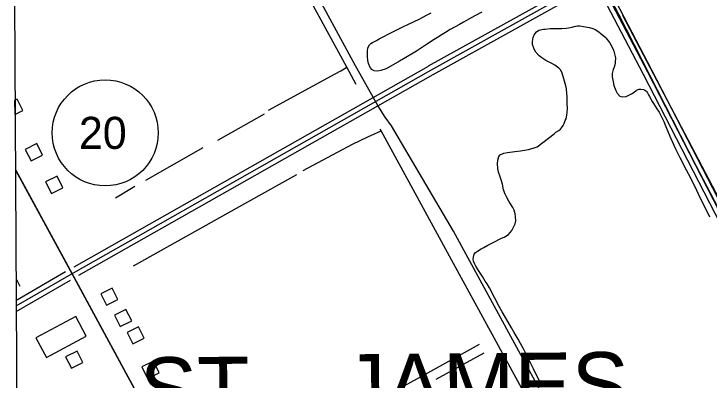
# Model space of a CAD drawing. Extents: x 3477039 to 3515015, y 546746 to 572297.
# Drawn here: x 3481169 to 3483333, y 568545 to 569685 of the extents above; entities that cross this region are included whole.
import ezdxf

# ---------------------------------------------------------------- set-up
doc = ezdxf.new("R2010")
doc.units = 0
for name, color, linetype in [('V-BLDG-OTLN', 7, 'Continuous'), ('V-DTCH-CNTR', 7, 'Continuous'), ('V-GRID-FRAM', 7, 'Continuous'), ('V-ROAD-CNTR', 7, 'Continuous'), ('V-ROAD-IDEN', 7, 'Continuous'), ('V-SITE-VEGE', 7, 'Continuous'), ('V-TOPO-GNAM-IDEN', 7, 'Continuous'), ('V-TOPO-SHOR', 7, 'Continuous')]:
    doc.layers.add(name, color=color, linetype=linetype)

msp = doc.modelspace()

# ---------------------------------------------------------------- linework, layer by layer
at = {"layer": 'V-BLDG-OTLN'}
msp.add_line((3481170.7, 569415.7), (3481170.9, 569371.1), dxfattribs=at)
msp.add_lwpolyline([(3481170.9, 569371.1), (3481196.2, 569383.7), (3481178.3, 569419.5), (3481170.7, 569415.7)], dxfattribs=at)
for points in [[(3481204, 569263), (3481221.8, 569227.2), (3481257.6, 569245.1), (3481239.7, 569280.9)], [(3481267.3, 569161.6), (3481285.1, 569125.8), (3481320.9, 569143.7), (3481303, 569179.4)], [(3481438.8, 568813.3), (3481456.6, 568777.5), (3481492.4, 568795.4), (3481474.5, 568831.2)], [(3481481.6, 568746.8), (3481499.4, 568711.1), (3481535.2, 568728.9), (3481517.3, 568764.7)], [(3481361.2, 568742.7), (3481237, 568676), (3481269.7, 568615), (3481394, 568681.7)], [(3481520.7, 568692.9), (3481538.5, 568657.1), (3481574.3, 568675), (3481556.4, 568710.8)], [(3481383.4, 568599.4), (3481365.1, 568635), (3481329.6, 568616.8), (3481347.8, 568581.2)], [(3481567.1, 568585.4), (3481585, 568549.6), (3481620.8, 568567.5), (3481602.9, 568603.3)]]:
    msp.add_lwpolyline(points, close=True, dxfattribs=at)
at = {"layer": 'V-DTCH-CNTR'}
for points in [[(3483152.3, 567881), (3482817.9, 568493.6), (3482537.7, 569008.8), (3482344, 569335.8), (3482325, 569363.3), (3482301.6, 569399.7), (3482232.6, 569523.3), (3481982.2, 569984.8)], [(3483992.7, 567895.7), (3483771.5, 568306), (3483623.2, 568581.2), (3483293.1, 569211.6), (3483052.3, 569682.7), (3482994.5, 569792.9)]]:
    msp.add_lwpolyline(points, dxfattribs=at)
at = {"layer": 'V-GRID-FRAM'}
msp.add_lwpolyline([(3481168.5, 570290.2), (3512800, 570478.9), (3512916.4, 552296.1), (3481269, 552107.3), (3481168.5, 570290.2)], dxfattribs=at)
at = {"layer": 'V-ROAD-CNTR'}
for points in [[(3483889, 570301.2), (3482465.8, 569508.5)], [(3482966.6, 569804.6), (3482458.5, 569521.6)], [(3485261.6, 565506.4), (3485151.8, 565691.2), (3485013.6, 565948.4), (3484992.5, 565993.9), (3484975.8, 566037.3), (3484914.3, 566147.8), (3484687.5, 566575.9), (3484376.6, 567150.9), (3484166, 567559.5), (3483812.6, 568215.1), (3483402.5, 568997.3), (3483141.9, 569503.2), (3482987.8, 569799.2)], [(3483392.2, 569050.1), (3483155.3, 569510.1), (3483007.8, 569793.2)], [(3482981.6, 569778.6), (3482473.1, 569495.4)], [(3483369.4, 569028.9), (3483128.6, 569496.3), (3482981.6, 569778.6)], [(3482465.8, 569508.5), (3481345.6, 568873.5), (3481175, 568774.6)], [(3482458.4, 569521.5), (3481355.4, 568896.3)], [(3482473.2, 569495.4), (3481369.7, 568869.9)], [(3481172.9, 569200), (3481356.5, 568862.8)], [(3481174.1, 569197.8), (3481348.7, 568877.3), (3482470.5, 566807), (3482914.2, 565989.7)], [(3481329.3, 568881.4), (3481174.2, 568791.4)], [(3481343.7, 568855), (3481174.3, 568756.8)], [(3481356.5, 568862.8), (3482479, 566791.3)], [(3481729.6, 568171.6), (3481980.7, 568306), (3482015.3, 568324.5), (3482224.5, 568439.5), (3482457.4, 568567.6), (3482618.3, 568656.1)], [(3482483.6, 568547.8), (3482632.7, 568629.8)]]:
    msp.add_lwpolyline(points, dxfattribs=at)
at = {"layer": 'V-ROAD-IDEN'}
msp.add_circle((3481452.9, 569314.4), 165, dxfattribs=at)
at = {"layer": 'V-SITE-VEGE'}
for points in [[(3482625.6, 569690.5), (3482603.6, 569679.2), (3482568.8, 569659.5), (3482556.1, 569652), (3482527.4, 569635.8), (3482511.9, 569626.7), (3482502.4, 569620.8), (3482487.3, 569611.7), (3482476.9, 569604.8), (3482453, 569589.6), (3482434.3, 569577.2), (3482421.9, 569569.2), (3482389.2, 569549.1), (3482369.6, 569537.8), (3482327.4, 569513.9), (3482311.5, 569508.1), (3482301.6, 569506.5), (3482289.8, 569507.7), (3482283.4, 569511.6), (3482277.7, 569518.3), (3482272.1, 569530.8), (3482270.3, 569539.9), (3482269.6, 569552.4), (3482269.3, 569560.5), (3482269.3, 569568.6), (3482270.7, 569579.5), (3482275.2, 569588.1), (3482279.6, 569592.2), (3482285.5, 569596.2), (3482297, 569602.2), (3482306.1, 569607.5), (3482322.2, 569615.8), (3482334.2, 569621.9), (3482354.5, 569632.2), (3482381.5, 569645.5), (3482395, 569651.9), (3482432.3, 569669.2), (3482453.6, 569680.5), (3482468.2, 569688.5)], [(3482731.1, 569040.2), (3482730.8, 569053.5), (3482729.4, 569061.8), (3482725.8, 569073.6), (3482722.1, 569081.7), (3482715.2, 569093.8), (3482709.7, 569101.9), (3482701.9, 569114.8), (3482697.7, 569123.9), (3482693.3, 569136.8), (3482689.6, 569154.9), (3482685.6, 569167.7), (3482682.3, 569177.1), (3482676.9, 569192.2), (3482674.9, 569202.9), (3482674.5, 569219.3), (3482675.1, 569229.5), (3482678.1, 569241), (3482682.6, 569245.8), (3482694, 569251.3), (3482705.5, 569253.6), (3482728, 569256), (3482746.2, 569258.5), (3482771.1, 569263.1), (3482788.7, 569267.8), (3482797.5, 569270.7), (3482851, 569311.1), (3482852.9, 569313.7), (3482855.5, 569316.1), (3482865.3, 569321.5), (3482870.7, 569325.9), (3482873.8, 569330), (3482878.3, 569337.5), (3482881.5, 569343.6), (3482885.4, 569352.4), (3482887.8, 569358.6), (3482890.3, 569370), (3482891.1, 569377.8), (3482891.9, 569390.1), (3482891.6, 569406), (3482890.8, 569428.1), (3482890.1, 569437.5), (3482888.9, 569451.9), (3482887, 569461.3), (3482880.3, 569482.5), (3482875.6, 569500.2), (3482871.2, 569509.9), (3482865.4, 569516.2), (3482852.7, 569524.9), (3482843.4, 569529.9), (3482825.2, 569539.3), (3482812.1, 569548), (3482803.9, 569554.3), (3482793.8, 569565.8), (3482788.9, 569575), (3482783.6, 569589.6), (3482783.3, 569598.7), (3482784.9, 569611.7), (3482788.2, 569619.6), (3482795.9, 569629.4), (3482803.4, 569634.1), (3482817.3, 569637.2), (3482822.3, 569637.7), (3482838.3, 569638.9), (3482848.6, 569639.2), (3482864.8, 569639.1), (3482874.4, 569639.4), (3482887.7, 569640), (3482895.8, 569641.3), (3482906.7, 569643.6), (3482913.3, 569645.6), (3482923.7, 569647.2), (3482931.1, 569647.2), (3482941.7, 569646), (3482961.2, 569642.5), (3482971.2, 569639.5), (3482978.7, 569636.4), (3482989.9, 569629.1), (3482997.4, 569623.2), (3483008.2, 569613.3), (3483011.4, 569610.2), (3483023.1, 569595.9), (3483027.4, 569588.9), (3483033.3, 569576.9), (3483036.4, 569568.7), (3483040, 569556), (3483041.2, 569547.7), (3483041.1, 569534.8), (3483040.5, 569530.9), (3483037.3, 569519.3), (3483034.5, 569511.8), (3483031.5, 569499.5), (3483031.4, 569489.2), (3483033.9, 569472.9), (3483037, 569462.2), (3483042.4, 569446.5), (3483046.8, 569437.6), (3483055.4, 569428.9), (3483062.9, 569426.3), (3483074.4, 569427.9), (3483081.6, 569430.4)], [(3483081.6, 569430.4), (3483091.6, 569435.5), (3483097.1, 569439.2), (3483105.3, 569445), (3483107.5, 569447.2), (3483115.4, 569450.5), (3483121, 569451), (3483128.7, 569449.7), (3483132.9, 569447.8), (3483137.9, 569444.6), (3483139.5, 569442.1), (3483141.3, 569439.5), (3483144.8, 569433.2), (3483147.9, 569427.8), (3483156.3, 569411.9), (3483159.8, 569406), (3483170, 569389.7), (3483177.3, 569378.4), (3483182.7, 569368.5), (3483191.7, 569350), (3483197.8, 569336.1), (3483214.4, 569296.8), (3483228.7, 569264.2), (3483242, 569238.2), (3483262.2, 569199.2), (3483274.8, 569174), (3483294.1, 569135.9)], [(3483294.1, 569135.9), (3483306.7, 569109.5), (3483320.7, 569081.2), (3483334.7, 569052.6)], [(3482811.3, 568530), (3482803.6, 568544.8), (3482793.1, 568566.6), (3482786.7, 568580.1), (3482776.3, 568600.8), (3482762.7, 568627.4), (3482756.5, 568640), (3482745.9, 568658.8), (3482738.4, 568671.6), (3482726.4, 568693.1), (3482717.8, 568707.7), (3482706, 568727.1), (3482698.7, 568739.7), (3482689, 568756.7), (3482675.7, 568780.9), (3482671, 568790.3), (3482666, 568799.8), (3482659.1, 568813.6), (3482654.2, 568822.9), (3482649.3, 568831.7), (3482641.8, 568844.3), (3482636.3, 568852.8), (3482627.7, 568866.7), (3482615.5, 568885.9), (3482611.9, 568891.1), (3482606.6, 568899.3), (3482603.3, 568905.2), (3482599.7, 568915), (3482599, 568920.9), (3482599.2, 568927.1), (3482602, 568936.3), (3482606.1, 568941.5), (3482611.8, 568946.4), (3482623.1, 568953.5), (3482631.4, 568957.9), (3482644.6, 568964.5), (3482664.7, 568975), (3482681, 568983.8), (3482686.3, 568986.3), (3482695, 568990.1), (3482700.6, 568993.2), (3482708.3, 568998.3), (3482713.4, 569003.7), (3482718.4, 569010.3), (3482723, 569018.3), (3482728.8, 569031.2), (3482731.1, 569040.2)]]:
    msp.add_lwpolyline(points, dxfattribs=at)
at = {"layer": 'V-TOPO-SHOR'}
for p, q in [((3483063.5, 569680.4), (3483406.1, 569028)), ((3481803.6, 569292.1), (3481949.3, 569373.3)), ((3481579.7, 569167.5), (3481758.3, 569269.1)), ((3481484.9, 569112), (3481545.4, 569148.6))]:
    msp.add_line(p, q, dxfattribs=at)
for points in [[(3482234.6, 569464.6), (3482204.9, 569519.2), (3482076.2, 569755.9), (3481954.5, 569989.4)], [(3481961.7, 569385.6), (3482169.1, 569497.9), (3482186.9, 569507.4), (3482204.9, 569519.2)], [(3482068.8, 569196.9), (3482222.6, 569279.5), (3482270.7, 569302.5), (3482311.6, 569321.2)], [(3483090, 567889), (3482835.6, 568362.9), (3482543.2, 568895.9), (3482311.6, 569321.2), (3482309, 569325.9)], [(3481541.2, 568900.4), (3481897, 569099.4), (3482049.5, 569184.7)], [(3481188.5, 568835.7), (3481176.4, 568858.7)]]:
    msp.add_lwpolyline(points, dxfattribs=at)

# ---------------------------------------------------------------- texts
at = {"layer": 'V-ROAD-IDEN'}
msp.add_text('20', height=100, dxfattribs=at).set_placement((3481371, 569264.4))
at = {"layer": 'V-TOPO-GNAM-IDEN'}
for s, p in [('ST.', (3481561.5, 568414.9)), ('JAMES', (3482192.8, 568424.7))]:
    msp.add_text(s, height=200, rotation=0.4893, dxfattribs=at).set_placement(p)

doc.saveas('drawing.dxf')
